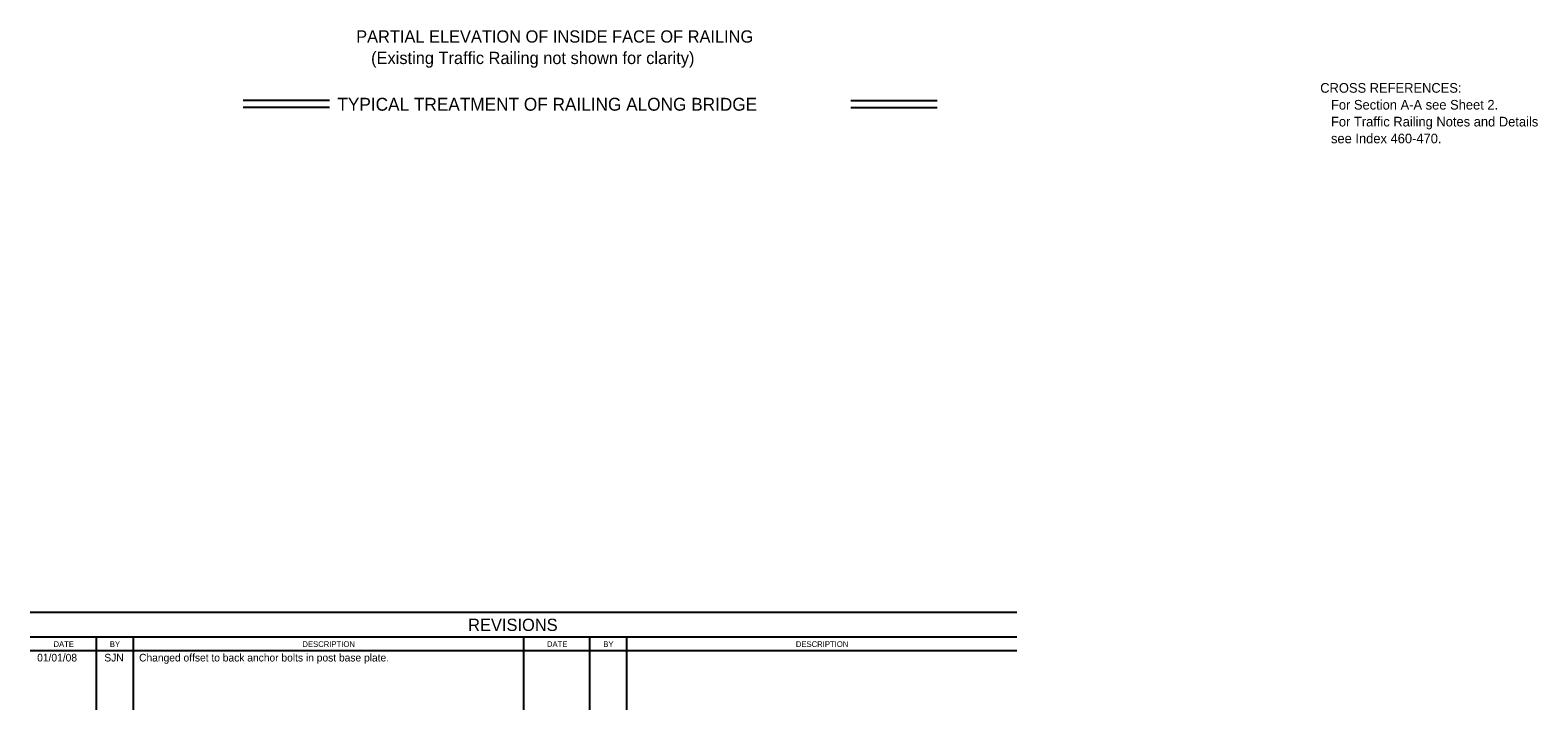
# Model space of a CAD drawing. Extents: x 21516.9 to 21586.2, y 56154.4 to 56193.6.
# Drawn here: x 21516.88 to 21548.37, y 56154.43 to 56168.62 of the extents above; entities that cross this region are included whole.
import ezdxf

# ---------------------------------------------------------------- set-up
doc = ezdxf.new("R2010")
doc.units = 0
for name, color, linetype in [('PlotBorder_dp', 7, 'Continuous'), ('SheetBorder_dp', 7, 'Continuous'), ('SheetLines_dp', 7, 'Continuous')]:
    doc.layers.add(name, color=color, linetype=linetype)

msp = doc.modelspace()

# ---------------------------------------------------------------- linework, layer by layer
at = {"layer": 'PlotBorder_dp'}
for p, q in [((21523.131, 56167.152), (21521.324, 56167.152)), ((21534.015, 56167.152), (21535.821, 56167.152)), ((21523.131, 56167.01), (21521.324, 56167.01)), ((21534.015, 56167.01), (21535.821, 56167.01))]:
    msp.add_line(p, q, dxfattribs=at)
at = {"layer": 'SheetLines_dp'}
for p, q in [((21537.488, 56156.459), (21516.877, 56156.459)), ((21537.488, 56155.944), (21516.877, 56155.944)), ((21518.253, 56155.944), (21518.253, 56154.429)), ((21519.027, 56155.944), (21519.027, 56154.429)), ((21527.183, 56155.944), (21527.183, 56154.429)), ((21528.559, 56155.944), (21528.559, 56154.429)), ((21529.333, 56155.944), (21529.333, 56154.429)), ((21516.877, 56155.671), (21537.488, 56155.671))]:
    msp.add_line(p, q, dxfattribs=at)

# ---------------------------------------------------------------- texts
at = {"layer": 'PlotBorder_dp'}
for s, height, p in [('PARTIAL ELEVATION OF INSIDE FACE OF RAILING', 0.256, (21523.686, 56168.364)), ('(Existing Traffic Railing not shown for clarity)', 0.256, (21523.998, 56167.916)), ('CROSS REFERENCES:', 0.2016, (21543.822, 56167.317)), ('   For Section A-A see Sheet 2.', 0.2016, (21543.822, 56166.965)), ('   For Traffic Railing Notes and Details ', 0.2016, (21543.822, 56166.613)), ('   see Index 460-470.', 0.2016, (21543.822, 56166.261))]:
    msp.add_text(s, height=height, dxfattribs=at).set_placement(p)
at = {"layer": 'SheetBorder_dp'}
for s, height, p in [('TYPICAL TREATMENT OF RAILING ALONG BRIDGE', 0.2688, (21523.294, 56166.942)), ('REVISIONS', 0.2567, (21526.025, 56156.076)), ('BY', 0.1201, (21518.541, 56155.742)), ('BY', 0.1201, (21528.847, 56155.742)), ('01/01/08', 0.16, (21517.023, 56155.439)), ('SJN', 0.16, (21518.426, 56155.439)), ('Changed offset to back anchor bolts in post base plate.', 0.16, (21519.152, 56155.439))]:
    msp.add_text(s, height=height, dxfattribs=at).set_placement(p)
for s, height, rotation, p in [('DATE', 0.1196, 359.8693, (21517.365, 56155.742)), ('DESCRIPTION', 0.12007, 0.0498, (21522.563, 56155.741)), ('DATE', 0.1196, 359.8693, (21527.671, 56155.742)), ('DESCRIPTION', 0.12007, 0.0498, (21532.869, 56155.741))]:
    msp.add_text(s, height=height, rotation=rotation, dxfattribs=at).set_placement(p)

doc.saveas('drawing.dxf')
